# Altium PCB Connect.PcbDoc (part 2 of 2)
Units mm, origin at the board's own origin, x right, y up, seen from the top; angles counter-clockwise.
Board outline 500 x 50 mm, 2 copper layers (Top Layer, Bottom Layer); 349 components, 200 nets, 1152 pads, 307 vias.
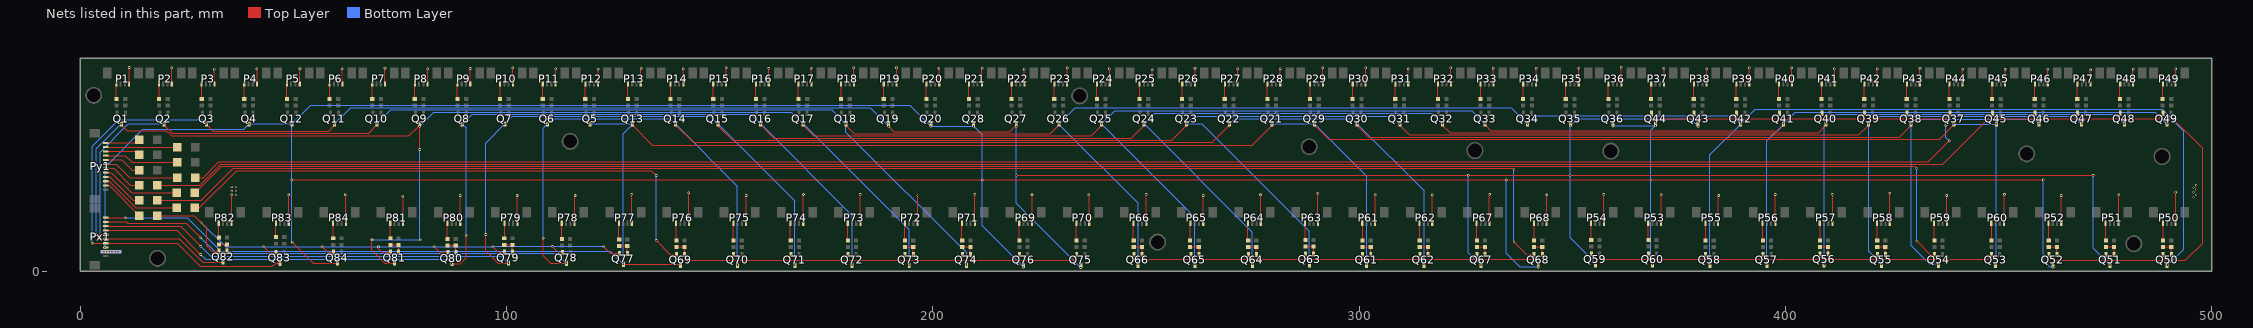
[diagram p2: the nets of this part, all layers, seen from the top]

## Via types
v1: diameter 0.6, hole 0.3, Top Layer to Bottom Layer, 196 vias
v2: diameter 0.5, hole 0.3, Top Layer to Bottom Layer, 111 vias

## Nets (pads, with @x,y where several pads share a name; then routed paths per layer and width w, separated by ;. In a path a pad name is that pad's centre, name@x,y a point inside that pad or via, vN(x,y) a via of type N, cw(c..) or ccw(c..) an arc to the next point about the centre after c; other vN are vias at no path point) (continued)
NetD6_1: D6.1 Q37.2 Q38.2 Q39.2 Q40.2 Q41.2 Q42.2 Q43.2 Q44.2 | length 499.5
  Top Layer w0.254: D6.1@26.992,21.971 28.829,21.971 32.512,25.654 433.451,25.654 v1(438.404,30.607) ; Q44.2@368.556,37.064 368.556,36.828 369.57,35.814 378.587,35.814 ; Q43.2@378.552,37.064 378.552,35.849 378.587,35.814 ; Q42.2@388.548,37.064 388.548,35.886 388.62,35.814 ; Q41.2@398.544,37.064 398.544,35.832 398.526,35.814 ; Q40.2@408.54,37.064 408.54,35.833 408.559,35.814 ; Q39.2@418.536,37.064 418.536,35.885 418.465,35.814 ; Q38.2@428.532,37.064 428.532,35.848 428.498,35.814 ; v1(437.642,34.29) 437.642,35.814 ; Q37.2@438.528,37.064 438.528,36.7 437.642,35.814 ; 378.587,35.814 388.62,35.814 ; 388.62,35.814 398.526,35.814 ; 398.526,35.814 408.559,35.814 ; 408.559,35.814 418.465,35.814 ; 418.465,35.814 428.498,35.814 ; 428.498,35.814 437.642,35.814
  Bottom Layer w0.254: v1(437.642,34.29) 437.642,31.369 v1(438.404,30.607)
NetD7_1: D7.1 Q45.2 Q46.2 Q47.2 Q48.2 Q49.2 Q50.2 Q51.2 Q52.2 | length 558.7
  Top Layer w0.254: D7.1@18.102,20.193 28.067,20.193 33.02,25.146 436.927,25.146 Q45.2@448.524,36.743 ; Q45.2@448.524,37.064 Q45.2@448.524,36.743 ; Q46.2@458.52,37.064 458.52,35.864 458.47,35.814 ; Q52.2@461.759,3.937 461.759,3.569 462.788,2.54 475.107,2.54 ; Q47.2@468.516,37.064 468.516,35.827 468.503,35.814 ; Q51.2@475.171,3.937 475.171,2.604 475.107,2.54 ; Q48.2@478.512,37.064 478.512,35.838 478.536,35.814 ; Q49.2@488.508,37.064 Q49.2@488.508,36.769 ; Q50.2@488.583,3.937 488.583,2.54 ; Q45.2@448.524,36.743 449.453,35.814 458.47,35.814 ; 458.47,35.814 468.503,35.814 ; 468.503,35.814 478.536,35.814 ; 475.107,2.54 488.583,2.54 ; 478.536,35.814 487.553,35.814 Q49.2@488.508,36.769 ; Q49.2@488.508,36.769 488.508,36.764 489.331,35.941 490.728,35.941 497.84,28.829 497.84,6.604 493.776,2.54 488.583,2.54
NetD8_1: D8.1 Q53.2 Q54.2 Q55.2 Q56.2 Q57.2 Q58.2 Q59.2 Q60.2 | length 531.3
  Top Layer w0.254: D8.1@26.865,18.415 27.007,18.415 33.23,24.638 430.276,24.638 v2(430.784,24.13) ; Q59.2@354.464,4.064 354.464,3.803 355.473,2.794 381.254,2.794 ; 367.876,2.921 Q60.2@367.876,4.064 ; Q58.2@381.287,3.937 381.287,2.827 381.254,2.794 ; Q57.2@394.699,3.937 394.699,2.811 394.716,2.794 ; Q56.2@408.111,3.937 408.111,2.854 408.051,2.794 ; Q55.2@421.523,3.937 421.523,2.804 421.513,2.794 ; v2(430.784,7.112) 433.959,3.937 Q54.2@434.935,3.937 434.935,2.794 ; Q53.2@448.347,3.937 448.347,3.593 447.548,2.794 434.935,2.794 ; 381.254,2.794 394.716,2.794 ; 394.716,2.794 408.051,2.794 ; 408.051,2.794 421.513,2.794 ; 421.513,2.794 434.935,2.794
  Bottom Layer w0.254: v2(430.784,7.112) v2(430.784,24.13)
NetD9_1: D9.1 Q61.2 Q62.2 Q63.2 Q64.2 Q65.2 Q66.2 Q67.2 Q68.2 | length 446.6
  Top Layer w0.254: D9.1@18.102,16.637 28.448,16.637 35.941,24.13 336.042,24.13 v2(336.296,23.876) ; Q66.2@247.168,3.937 247.168,3.657 248.031,2.794 260.477,2.794 ; Q65.2@260.499,3.937 260.499,2.816 260.477,2.794 ; Q64.2@273.992,3.937 273.992,2.868 274.066,2.794 ; Q63.2@287.404,4.064 287.404,2.797 287.401,2.794 ; Q61.2@300.816,3.937 300.816,2.874 300.736,2.794 ; Q62.2@314.228,3.937 314.228,2.824 314.198,2.794 ; Q67.2@327.64,3.937 327.64,2.814 327.66,2.794 ; v2(336.296,6.985) 339.344,3.937 Q68.2@341.052,3.937 341.052,3.613 340.233,2.794 327.66,2.794 ; 260.477,2.794 274.066,2.794 ; 274.066,2.794 287.401,2.794 ; 287.401,2.794 300.736,2.794 ; 300.736,2.794 314.198,2.794 ; 314.198,2.794 327.66,2.794
  Bottom Layer w0.254: v2(336.296,6.985) v2(336.296,23.876)
NetD10_1: D10.1 Q69.2 Q70.2 Q71.2 Q72.2 Q73.2 Q74.2 Q75.2 Q76.2 | length 237.7
  Top Layer w0.254: D10.1@26.865,14.859 27.94,14.859 36.703,23.622 133.985,23.622 v1(135.128,22.479) ; v1(135.128,7.239) 138.43,3.937 Q69.2@139.873,3.937 139.873,3.637 140.97,2.54 153.285,2.54 ; Q70.2@153.285,3.937 153.285,2.54 ; Q71.2@166.697,3.937 166.697,2.613 166.624,2.54 ; Q72.2@180.109,3.937 180.109,2.563 180.086,2.54 ; Q73.2@193.521,3.937 193.521,2.567 193.548,2.54 ; Q74.2@206.933,3.937 206.933,2.617 207.01,2.54 ; Q76.2@220.345,3.937 220.345,2.54 ; Q75.2@233.757,3.937 233.757,3.633 232.664,2.54 220.345,2.54 ; 153.285,2.54 166.624,2.54 ; 166.624,2.54 180.086,2.54 ; 180.086,2.54 193.548,2.54 ; 193.548,2.54 207.01,2.54 ; 207.01,2.54 220.345,2.54
  Bottom Layer w0.254: v1(135.128,7.239) 135.001,7.366 135.128,7.493 v1(135.128,22.479)
NetD11_1: D11.1 Q77.2 Q78.2 Q79.2 Q80.2 Q81.2 Q82.2 Q83.2 Q84.2 | length 141.6
  Top Layer w0.254: D11.1@18.102,13.081 26.797,13.081 v2(28.448,11.43) 29.718,10.16 29.718,5.969 31.008,4.679 Q82.2@32.578,4.679 ; v1(43.053,5.715) 44.363,4.405 Q83.2@45.913,4.405 ; v1(56.769,5.715) 58.039,4.445 Q84.2@59.402,4.445 ; v1(69.977,5.715) 69.977,5.334 70.866,4.445 Q81.2@72.814,4.445 ; v1(83.058,5.715) 84.455,4.318 Q80.2@86.226,4.318 ; v1(96.774,5.715) 98.044,4.445 Q79.2@99.51,4.445 ; v1(110.744,5.842) 112.181,4.405 Q78.2@113.096,4.405 ; v1(122.809,5.715) 124.333,4.191 Q77.2@126.461,4.191
  Bottom Layer w0.254: v2(28.448,11.43) 34.163,5.715 v1(43.053,5.715) v1(56.769,5.715) v1(69.977,5.715) v1(83.058,5.715) v1(96.774,5.715) 96.901,5.842 v1(110.744,5.842) 122.682,5.842 v1(122.809,5.715)
NetP1_4: P1.4 R85.2 | length 3.5
  Top Layer w0.254: P1.4@8.5,43.925 8.5,40.403 R85.2@8.509,40.394
NetP2_4: P2.4 R86.2 | length 3.5
  Top Layer w0.254: P2.4@18.5,43.925 18.5,40.402 R86.2@18.508,40.394
NetP3_4: P3.4 R87.2 | length 3.5
  Top Layer w0.254: P3.4@28.5,43.925 28.5,40.4 R87.2@28.506,40.394
NetP4_4: P4.4 R88.2 | length 3.5
  Top Layer w0.254: P4.4@38.5,43.925 38.5,40.399 R88.2@38.505,40.394
NetP5_4: P5.4 R89.2 | length 3.5
  Top Layer w0.254: P5.4@48.5,43.925 48.503,43.922 R89.2@48.503,40.394
NetP6_4: P6.4 R90.2 | length 3.5
  Top Layer w0.254: P6.4@58.5,43.925 58.502,43.923 R90.2@58.502,40.394
NetP7_4: P7.4 R91.2 | length 3.5
  Top Layer w0.254: R91.2@68.501,40.394 P7.4@68.501,43.924
NetP8_4: P8.4 R92.2 | length 3.5
  Top Layer w0.254: R92.2@78.499,40.394 P8.4@78.499,43.924
NetP9_4: P9.4 R93.2 | length 3.5
  Top Layer w0.254: R93.2@88.498,40.394 88.498,43.923 P9.4@88.5,43.925
NetP10_4: P10.4 R94.2 | length 3.5
  Top Layer w0.254: R94.2@98.496,40.394 98.496,43.921 P10.4@98.5,43.925
NetP11_4: P11.4 R95.2 | length 3.5
  Top Layer w0.254: R95.2@108.495,40.394 108.495,43.92 P11.4@108.5,43.925
NetP12_4: P12.4 R96.2 | length 3.5
  Top Layer w0.254: R96.2@118.494,40.394 118.494,43.919 P12.4@118.5,43.925
NetP13_4: P13.4 R97.2 | length 3.5
  Top Layer w0.254: R97.2@128.492,40.394 128.492,43.917 P13.4@128.5,43.925
NetP14_4: P14.4 R98.2 | length 3.5
  Top Layer w0.254: R98.2@138.491,40.394 138.491,43.916 P14.4@138.5,43.925
NetP15_4: P15.4 R99.2 | length 3.5
  Top Layer w0.254: R99.2@148.489,40.394 148.489,43.914 P15.4@148.5,43.925
NetP16_4: P16.4 R100.2 | length 3.5
  Top Layer w0.254: R100.2@158.488,40.394 158.488,43.913 P16.4@158.5,43.925
NetP17_4: P17.4 R101.2 | length 3.5
  Top Layer w0.254: R101.2@168.487,40.394 168.487,43.912 P17.4@168.5,43.925
NetP18_4: P18.4 R102.2 | length 3.5
  Top Layer w0.254: R102.2@178.485,40.394 178.485,43.91 P18.4@178.5,43.925
NetP19_4: P19.4 R103.2 | length 3.5
  Top Layer w0.254: R103.2@188.484,40.394 188.484,43.909 P19.4@188.5,43.925
NetP20_4: P20.4 R104.2 | length 3.5
  Top Layer w0.254: R104.2@198.482,40.394 198.482,43.907 P20.4@198.5,43.925
NetP21_4: P21.4 R105.2 | length 3.5
  Top Layer w0.254: R105.2@208.481,40.394 208.481,43.906 P21.4@208.5,43.925
NetP22_4: P22.4 R106.2 | length 3.5
  Top Layer w0.254: R106.2@218.48,40.394 218.48,43.905 P22.4@218.5,43.925
NetP23_4: P23.4 R107.2 | length 3.5
  Top Layer w0.254: R107.2@228.478,40.394 228.478,43.903 P23.4@228.5,43.925
NetP24_4: P24.4 R108.2 | length 3.5
  Top Layer w0.254: R108.2@238.477,40.394 238.477,43.902 P24.4@238.5,43.925
NetP25_4: P25.4 R109.2 | length 3.5
  Top Layer w0.254: R109.2@248.475,40.394 248.475,43.901 P25.4@248.5,43.925
NetP26_4: P26.4 R110.2 | length 3.5
  Top Layer w0.254: R110.2@258.474,40.394 258.474,43.899 P26.4@258.5,43.925
NetP27_4: P27.4 R111.2 | length 3.5
  Top Layer w0.254: R111.2@268.473,40.394 268.473,43.898 P27.4@268.5,43.925
NetP28_4: P28.4 R112.2 | length 3.5
  Top Layer w0.254: R112.2@278.471,40.394 278.471,43.896 P28.4@278.5,43.925
NetP29_4: P29.4 R113.2 | length 3.5
  Top Layer w0.254: R113.2@288.47,40.394 288.47,43.895 P29.4@288.5,43.925
NetP30_4: P30.4 R114.2 | length 3.5
  Top Layer w0.254: R114.2@298.468,40.394 298.468,43.894 P30.4@298.5,43.925
NetP31_4: P31.4 R115.2 | length 3.5
  Top Layer w0.254: R115.2@308.467,40.394 308.467,43.892 P31.4@308.5,43.925
NetP32_4: P32.4 R116.2 | length 3.5
  Top Layer w0.254: R116.2@318.466,40.394 318.466,43.891 P32.4@318.5,43.925
NetP33_4: P33.4 R117.2 | length 3.5
  Top Layer w0.254: R117.2@328.464,40.394 328.464,43.889 P33.4@328.5,43.925
NetP34_4: P34.4 R118.2 | length 3.5
  Top Layer w0.254: R118.2@338.463,40.394 338.463,43.888 P34.4@338.5,43.925
NetP35_4: P35.4 R119.2 | length 3.5
  Top Layer w0.254: R119.2@348.462,40.394 348.462,43.887 P35.4@348.5,43.925
NetP36_4: P36.4 R120.2 | length 3.5
  Top Layer w0.254: R120.2@358.46,40.394 358.46,43.885 P36.4@358.5,43.925
NetP37_4: P37.4 R121.2 | length 3.5
  Top Layer w0.254: R121.2@368.459,40.394 368.459,43.884 P37.4@368.5,43.925
NetP38_4: P38.4 R122.2 | length 3.5
  Top Layer w0.254: R122.2@378.457,40.394 378.457,43.882 P38.4@378.5,43.925
NetP39_4: P39.4 R123.2 | length 3.5
  Top Layer w0.254: R123.2@388.456,40.394 388.456,43.881 P39.4@388.5,43.925
NetP40_4: P40.4 R124.2 | length 3.5
  Top Layer w0.254: R124.2@398.455,40.394 398.455,43.88 P40.4@398.5,43.925
NetP41_4: P41.4 R125.2 | length 3.6
  Top Layer w0.254: R125.2@408.453,40.394 408.453,43.878 P41.4@408.5,43.925
NetP42_4: P42.4 R126.2 | length 3.6
  Top Layer w0.254: R126.2@418.452,40.394 418.452,43.877 P42.4@418.5,43.925
NetP43_4: P43.4 R127.2 | length 3.6
  Top Layer w0.254: R127.2@428.45,40.394 428.45,43.875 P43.4@428.5,43.925
NetP44_4: P44.4 R128.2 | length 3.6
  Top Layer w0.254: R128.2@438.449,40.394 438.449,43.874 P44.4@438.5,43.925
NetP45_4: P45.4 R129.2 | length 3.6
  Top Layer w0.254: R129.2@448.448,40.394 448.448,43.873 P45.4@448.5,43.925
NetP46_4: P46.4 R130.2 | length 3.6
  Top Layer w0.254: R130.2@458.446,40.394 458.446,43.871 P46.4@458.5,43.925
NetP47_4: P47.4 R131.2 | length 3.6
  Top Layer w0.254: R131.2@468.445,40.394 468.445,43.87 P47.4@468.5,43.925
NetP48_4: P48.4 R132.2 | length 3.6
  Top Layer w0.254: R132.2@478.443,40.394 478.443,43.868 P48.4@478.5,43.925
NetP49_4: P49.4 R133.2 | length 3.6
  Top Layer w0.254: R133.2@488.442,40.394 488.442,43.867 P49.4@488.5,43.925
NetP50_4: P50.4 R134.2 | length 4
  Top Layer w0.254: P50.4@488.5,11.268 488.569,11.199 R134.2@488.569,7.247
NetP51_4: P51.4 R135.2 | length 4
  Top Layer w0.254: P51.4@475.088,11.268 475.156,11.2 R135.2@475.156,7.247
NetP52_4: P52.4 R136.2 | length 4
  Top Layer w0.254: P52.4@461.677,11.268 461.744,11.2 R136.2@461.744,7.247
NetP53_4: P53.4 R137.2 | length 3.9
  Top Layer w0.254: P53.4@367.795,11.268 367.858,11.205 R137.2@367.858,7.374
NetP54_4: P54.4 R138.2 | length 3.9
  Top Layer w0.254: P54.4@354.383,11.268 354.445,11.206 R138.2@354.445,7.374
NetP55_4: P55.4 R139.2 | length 4
  Top Layer w0.254: P55.4@381.207,11.268 381.27,11.205 R139.2@381.27,7.247
NetP56_4: P56.4 R140.2 | length 4
  Top Layer w0.254: P56.4@394.618,11.268 394.682,11.204 R140.2@394.682,7.247
NetP57_4: P57.4 R141.2 | length 4
  Top Layer w0.254: P57.4@408.03,11.268 408.095,11.203 R141.2@408.095,7.247
NetP58_4: P58.4 R142.2 | length 4
  Top Layer w0.254: P58.4@421.442,11.268 421.507,11.203 R142.2@421.507,7.247
NetP59_4: P59.4 R143.2 | length 4
  Top Layer w0.254: P59.4@434.853,11.268 434.919,11.202 R143.2@434.919,7.247
NetP60_4: P60.4 R144.2 | length 4
  Top Layer w0.254: P60.4@448.265,11.268 448.332,11.201 R144.2@448.332,7.247
NetP61_4: P61.4 R145.2 | length 4
  Top Layer w0.254: P61.4@300.736,11.268 300.796,11.209 R145.2@300.796,7.247
NetP62_4: P62.4 R146.2 | length 4
  Top Layer w0.254: P62.4@314.148,11.268 314.208,11.208 R146.2@314.208,7.247
NetP63_4: P63.4 R147.2 | length 4
  Top Layer w0.254: P63.4@287.325,11.268 287.325,7.374 R147.2@287.383,7.374
NetP64_4: P64.4 R148.2 | length 4.1
  Top Layer w0.254: P64.4@273.913,11.268 273.913,7.247 R148.2@273.971,7.247
NetP65_4: P65.4 R149.2 | length 4.3
  Top Layer w0.254: R149.2@260.42,6.985 P65.4@260.42,11.268
NetP66_4: P66.4 R150.2 | length 4.1
  Top Layer w0.254: P66.4@247.066,11.268 247.066,7.247 R150.2@247.146,7.247
NetP67_4: P67.4 R151.2 | length 4
  Top Layer w0.254: P67.4@327.56,11.268 327.62,11.207 R151.2@327.62,7.247
NetP68_4: P68.4 R152.2 | length 4
  Top Layer w0.254: P68.4@340.971,11.268 341.033,11.207 R152.2@341.033,7.247
NetP69_4: P69.4 R153.2 | length 4.1
  Top Layer w0.254: P69.4@220.243,11.268 220.243,7.247 R153.2@220.322,7.247
NetP70_4: P70.4 R154.2 | length 4.1
  Top Layer w0.254: P70.4@233.655,11.268 233.655,7.247 R154.2@233.734,7.247
NetP71_4: P71.4 R155.2 | length 4.1
  Top Layer w0.254: P71.4@206.832,11.268 206.832,7.247 R155.2@206.909,7.247
NetP72_4: P72.4 R156.2 | length 4.3
  Top Layer w0.254: P72.4@193.421,11.43 193.421,7.247 R156.2@193.497,7.247
NetP73_4: P73.4 R157.2 | length 4.1
  Top Layer w0.254: P73.4@180.01,11.268 180.01,7.247 R157.2@180.084,7.247
NetP74_4: P74.4 R158.2 | length 4.1
  Top Layer w0.254: P74.4@166.599,11.268 166.599,7.247 R158.2@166.672,7.247
NetP75_4: P75.4 R159.2 | length 4.1
  Top Layer w0.254: P75.4@153.187,11.268 153.187,7.247 R159.2@153.26,7.247
NetP76_4: P76.4 R160.2 | length 4.1
  Top Layer w0.254: P76.4@139.776,11.268 139.776,7.247 R160.2@139.847,7.247
NetP77_4: P77.4 R161.2 | length 4.1
  Top Layer w0.254: R161.2@126.365,7.247 R161.2@126.365,7.501 ; P77.4@126.365,11.303 R161.2@126.365,7.501 ; R161.2@126.435,7.501 R161.2@126.365,7.501
NetP78_4: P78.4 R162.2 | length 4.1
  Top Layer w0.254: R162.2@112.954,7.247 R162.2@112.954,7.628 ; P78.4@112.954,11.268 R162.2@112.954,7.628 ; R162.2@113.023,7.628 R162.2@112.954,7.628
NetP79_4: P79.4 R163.2 | length 3.9
  Top Layer w0.254: R163.2@99.434,7.755 R163.2@99.483,7.755 ; R163.2@99.561,7.374 P79.4@99.561,11.268
NetP80_4: P80.4 R164.2 | length 3.7
  Top Layer w0.254: P80.4@86.15,11.268 86.15,7.628 R164.2@86.198,7.628
NetP81_4: P81.4 R165.2 | length 3.4
  Top Layer w0.254: P81.4@72.72,11.049 72.72,7.755 R165.2@72.786,7.755
NetP82_4: P82.4 R166.2 | length 3.5
  Top Layer w0.254: P82.4@32.503,11.268 32.503,9.957 32.487,9.94 32.487,7.882 R166.2@32.549,7.882
NetP83_4: P83.4 R167.2 | length 3.1
  Top Layer w0.254: P83.4@45.898,11.049 45.898,8.009 R167.2@45.961,8.009
NetP84_4: P84.4 R168.2 | length 3.5
  Top Layer w0.254: R168.2@59.326,7.755 P84.4@59.326,11.268
P00: Px1.1 Q5.3 Q13.3 Q21.3 Q29.3 Q37.3 Q45.3 Q53.3 Q61.3 Q69.3 Q77.3 | length 581.6
  Top Layer w0.254: Px1.1@6.004,12.587 10.527,12.587 v1(10.541,12.573) ; Q77.3@127.411,1.691 140.569,1.691 Q69.3@140.823,1.437 ; Q13.3@129.603,34.564 129.603,34.227 134.239,29.591 274.955,29.591 279.543,34.179 v1(279.543,34.564) ; v1(289.56,34.544) 289.56,34.29 292.862,30.988 436.118,30.988 439.478,34.348 v1(439.478,34.564)
  Bottom Layer w0.254: v1(10.541,12.573) 25.146,12.573 33.02,4.699 124.333,4.699 v1(127.381,1.651) 127.381,32.258 v1(129.667,34.544) 129.647,34.564 v1(119.608,34.564) ; v1(279.543,34.564) 289.54,34.564 v1(289.56,34.544) 301.752,22.352 v1(301.752,1.778) ; v1(439.478,34.564) 439.498,34.544 v1(449.453,34.544) 449.453,1.905 v1(449.326,1.778)
P01: Px1.2 Q6.3 Q14.3 Q22.3 Q30.3 Q38.3 Q46.3 Q54.3 Q62.3 Q70.3 Q78.3 | length 624.4
  Top Layer w0.254: Px1.2@6.004,11.587 10.765,11.587 11.049,11.303 24.892,11.303 v1(28.321,7.874) ; v1(108.585,7.747) 108.585,3.683 110.363,1.905 v1(114.046,1.905) ; v1(139.599,34.564) 139.599,34.391 143.764,30.226 265.557,30.226 269.547,34.216 v1(269.547,34.564) ; v1(299.593,34.544) 299.593,34.163 302.26,31.496 426.72,31.496 429.482,34.258 v1(429.482,34.564)
  Bottom Layer w0.254: v1(28.321,7.874) 32.004,4.191 111.76,4.191 v1(114.046,1.905) ; v1(108.585,7.747) 108.585,33.537 v1(109.612,34.564) 110.862,35.814 138.349,35.814 v1(139.599,34.564) 154.178,19.985 v1(154.178,1.397) ; v1(269.547,34.564) 270.797,35.814 298.323,35.814 v1(299.593,34.544) 315.214,18.923 v1(315.214,1.778) ; v1(435.864,1.778) 433.705,1.778 429.482,6.001 v1(429.482,34.564) 430.605,35.687 458.347,35.687 v1(459.47,34.564)
P02: Px1.3 Q7.3 Q15.3 Q23.3 Q31.3 Q39.3 Q47.3 Q55.3 Q63.3 Q71.3 Q79.3 | length 638.3
  Top Layer w0.254: Px1.3@6.004,10.587 23.576,10.587 v1(28.321,5.842) ; v1(95.123,8.636) 95.123,4.826 98.044,1.905 v1(100.457,1.905) ; Q79.3@100.461,1.655 Q79.3@100.461,1.945 ; v1(149.595,34.564) 149.595,34.174 153.035,30.734 256.032,30.734 259.551,34.253 v1(259.551,34.564) ; v1(309.531,34.564) 309.531,34.258 311.785,32.004 417.195,32.004 419.486,34.295 v1(419.486,34.564)
  Bottom Layer w0.254: v1(28.321,5.842) 30.607,3.556 98.806,3.556 v1(100.457,1.905) ; v1(95.123,8.636) 95.123,30.071 v1(99.616,34.564) 101.374,36.322 147.837,36.322 v1(149.595,34.564) 167.64,16.519 v1(167.64,1.397) ; v1(288.29,1.905) 288.29,9.398 263.124,34.564 v1(259.551,34.564) 261.309,36.322 307.773,36.322 v1(309.531,34.564) ; v1(422.529,1.651) 419.486,4.694 v1(419.486,34.564) 421.244,36.322 467.741,36.322 v1(469.519,34.544)
P03: Px1.4 Q8.3 Q16.3 Q24.3 Q32.3 Q40.3 Q48.3 Q56.3 Q64.3 Q72.3 Q80.3 | length 639.5
  Top Layer w0.254: Px1.4@6.004,9.587 22.671,9.587 v1(28.321,3.937) ; v1(87.122,1.778) 89.154,1.778 90.551,3.175 v1(90.551,8.509) ; Q8.3@89.62,34.564 89.642,34.564 v1(89.662,34.544) ; v1(159.591,34.564) 159.591,34.338 162.687,31.242 246.507,31.242 249.555,34.29 v1(249.555,34.564) ; v1(319.532,34.559) 319.532,34.29 321.31,32.512 407.797,32.512 409.49,34.205 v1(409.49,34.564)
  Bottom Layer w0.254: v1(28.321,3.937) 29.464,2.794 86.106,2.794 v1(87.122,1.778) ; v1(90.551,8.509) 90.551,33.655 v1(89.662,34.544) 91.948,36.83 157.325,36.83 v1(159.591,34.564) 181.102,13.053 v1(181.102,1.397) ; v1(274.955,1.778) 274.955,9.164 v1(249.555,34.564) 252.075,37.084 317.007,37.084 v1(319.532,34.559) ; v1(409.067,1.524) 409.067,34.141 v1(409.49,34.564) 411.756,36.83 477.196,36.83 v1(479.462,34.564)
P04: Px1.5 Q1.3 Q9.3 Q17.3 Q25.3 Q33.3 Q41.3 Q49.3 Q57.3 Q65.3 Q73.3 Q81.3 | length 691.3
  Top Layer w0.254: v1(3.81,8.636) 5.955,8.636 Px1.5@6.004,8.587 ; v1(9.652,34.564) 9.652,34.417 11.049,33.02 20.193,33.02 21.463,31.75 77.089,31.75 79.375,34.036 v1(79.629,34.036) v1(79.629,28.575) ; v1(68.453,7.366) 68.453,4.953 71.461,1.945 Q81.3@73.764,1.945 ; v1(169.587,34.564) 169.587,34.248 172.085,31.75 237.109,31.75 239.559,34.2 v1(239.559,34.564) ; Q33.3@329.523,34.564 329.523,34.332 330.835,33.02 398.272,33.02 399.494,34.242 Q41.3@399.494,34.564
  Bottom Layer w0.254: v1(3.81,8.636) 3.81,28.722 v1(9.652,34.564) ; v1(68.453,7.366) v1(79.756,7.366) 79.629,7.493 v1(79.629,28.575) ; v1(79.629,34.036) 82.931,37.338 166.813,37.338 v1(169.587,34.564) 194.437,9.714 v1(194.437,1.397) ; v1(261.493,1.651) 261.493,12.63 v1(239.559,34.564) 242.714,37.719 326.39,37.719 v1(329.565,34.544) ; v1(395.605,1.651) 395.605,30.607 v1(399.542,34.544) 402.336,37.338 486.664,37.338 v1(489.458,34.544)
P05: Px1.6 Q2.3 Q10.3 Q18.3 Q26.3 Q34.3 Q42.3 Q50.3 Q58.3 Q66.3 Q74.3 Q82.3 | length 712.4
  Top Layer w0.254: v1(4.699,7.62) 5.971,7.62 Px1.6@6.004,7.587 23.274,7.587 28.702,2.159 33.508,2.159 Q82.3@33.528,2.179 ; v1(19.648,34.564) 19.648,34.327 21.59,32.385 67.691,32.385 69.628,34.322 v1(69.628,34.564) ; v1(179.583,34.564) 179.583,34.285 181.61,32.258 227.584,32.258 229.563,34.237 Q26.3@229.563,34.564
  Bottom Layer w0.254: v1(4.699,7.62) 4.699,27.94 11.323,34.564 v1(19.648,34.564) ; v1(69.628,34.564) 72.91,37.846 176.301,37.846 v1(179.583,34.564) 179.583,32.634 207.899,4.318 v1(207.899,1.397) ; v1(248.158,1.778) 248.158,15.969 v1(229.583,34.544) 233.393,38.354 335.661,38.354 v1(339.471,34.544) 341.376,36.449 387.604,36.449 v1(389.509,34.544) ; v1(382.27,1.778) 382.27,27.305 v1(389.509,34.544) ; v1(489.585,1.397) 493.395,5.207 493.395,32.893 488.315,37.973 392.938,37.973 v1(389.509,34.544)
P06: Px1.7 Q3.3 Q11.3 Q19.3 Q27.3 Q35.3 Q43.3 Q51.3 Q59.3 Q67.3 Q75.3 Q83.3 | length 699.8
  Top Layer w0.254: v1(2.794,6.604) 5.987,6.604 Px1.7@6.004,6.587 22.75,6.587 28.194,1.143 45.085,1.143 45.847,1.905 Q83.3@46.863,1.905 ; v1(29.644,34.564) 29.644,34.364 31.115,32.893 58.293,32.893 59.632,34.232 v1(59.632,34.564) ; Q19.3@189.579,34.564 189.579,34.068 v1(189.611,34.036) 190.881,32.766 218.059,32.766 219.329,34.036 v1(219.583,34.036) ; v2(219.587,22.483) v1(325.628,22.483) v2(349.504,22.483) v1(472.19,22.483) ; v1(234.696,0.889) Q75.3@234.823,0.889 ; v1(349.515,34.152) Q35.3@349.515,34.564 ; Q59.3@355.414,1.329 Q59.3@355.414,1.564 ; v1(379.476,34.036) Q43.3@379.603,34.036
  Bottom Layer w0.254: v1(2.794,6.604) 2.794,29.337 9.017,35.56 28.648,35.56 v1(29.644,34.564) ; v1(59.632,34.564) 63.422,38.354 185.293,38.354 v1(189.611,34.036) ; v1(219.583,34.036) 219.587,34.032 v2(219.587,22.483) 219.587,16.006 219.583,16.002 v1(234.696,0.889) ; v1(325.628,22.483) 325.628,4.399 v1(328.59,1.437) ; v1(355.473,1.905) 349.515,7.863 v1(349.515,34.152) 351.176,35.814 377.698,35.814 v1(379.476,34.036) ; v1(472.19,22.483) 472.19,5.376 472.186,5.372 v2(476.121,1.437)
P07: Px1.8 Q4.3 Q12.3 Q20.3 Q28.3 Q36.3 Q44.3 Q52.3 Q60.3 Q68.3 Q76.3 Q84.3 | length 812.6
  Top Layer w0.254: v1(49.636,21.463) v2(211.582,21.463) v1(334.518,21.463) v2(368.427,21.463) v1(460.502,21.463) ; v1(49.784,6.858) 54.697,1.945 Q84.3@60.352,1.945 Q84.3@60.352,1.651 ; v1(199.517,34.036) 199.575,34.094 Q20.3@199.575,34.564 ; v1(221.234,1.016) Q76.3@221.361,1.016 ; Q68.3@342.002,1.437 342.002,1.025 v1(342.011,1.016) ; Q36.3@359.51,34.564 359.51,34.063 v1(359.537,34.089) ; Q44.3@369.443,34.163 v1(369.496,34.11)
  Bottom Layer w0.254: v1(5.842,5.588) 5.842,24.384 14.732,33.274 38.35,33.274 v1(39.64,34.564) v1(49.636,34.564) ; v1(49.784,6.858) 49.636,7.006 v1(49.636,21.463) v1(49.636,34.564) ; v1(221.234,1.016) 211.582,10.668 v2(211.582,21.463) 211.582,32.004 v1(209.55,34.036) v1(199.517,34.036) 194.564,38.989 54.061,38.989 v1(49.636,34.564) ; v1(334.518,21.463) 334.518,4.191 337.693,1.016 v1(342.011,1.016) ; v1(359.537,34.089) v1@369.475,34.089 ; v1(368.808,1.651) 368.427,2.032 v2(368.427,21.463) 368.427,33.041 v1@369.475,34.089 ; v1(369.496,34.11) v1@369.475,34.089 ; v1(460.502,21.463) 460.502,2.413 461.899,1.016 v1(462.661,1.016)
P11: D1.2 Py1.1 | length 8.2
  Top Layer w0.254: Py1.1@6.004,30.138 13.179,30.138 D1.2@13.902,30.861
P12: D2.2 Py1.2 | length 16.8
  Top Layer w0.254: Py1.2@6.004,29.138 22.737,29.138 D2.2@22.792,29.083
P13: D3.2 Py1.3 | length 8.2
  Top Layer w0.254: Py1.3@6.004,28.138 13.069,28.138 D3.2@13.902,27.305
P14: D4.2 Py1.4 | length 17.5
  Top Layer w0.254: Py1.4@6.004,27.138 10.581,27.138 12.192,25.527 D4.2@22.792,25.527
P15: D5.2 Py1.5 | length 8.9
  Top Layer w0.254: Py1.5@6.004,26.138 9.803,26.138 12.192,23.749 D5.2@13.902,23.749
P16: D6.2 Py1.6 | length 18.1
  Top Layer w0.254: Py1.6@6.004,25.138 8.517,25.138 11.684,21.971 D6.2@22.792,21.971
P17: D7.2 Py1.7 | length 9.5
  Top Layer w0.254: Py1.7@6.004,24.138 7.866,24.138 11.811,20.193 D7.2@13.902,20.193
P24: D11.2 Py1.11 | length 10.8
  Top Layer w0.254: Py1.11@6.004,20.138 6.845,20.138 D11.2@13.902,13.081
P25: D10.2 Py1.10 | length 19.3
  Top Layer w0.254: Py1.10@6.004,21.138 6.802,21.138 13.081,14.859 D10.2@22.665,14.859
P26: D9.2 Py1.9 | length 10.2
  Top Layer w0.254: Py1.9@6.004,22.138 6.945,22.138 12.446,16.637 D9.2@13.902,16.637
P27: D8.2 Py1.8 | length 18.6
  Top Layer w0.254: Py1.8@6.004,23.138 7.342,23.138 12.065,18.415 D8.2@22.665,18.415
RECORD: Q50.1 R50.2 R134.1 | length 3.7
  Top Layer w0.254: R134.1@488.569,5.707 R50.2@490.474,5.707 490.474,3.946 Q50.1@490.483,3.937
REPLAY: Q74.1 R74.2 R155.1 | length 3.7
  Top Layer w0.254: R155.1@206.909,5.707 R74.2@208.814,5.707 208.833,5.707 Q74.1@208.833,3.937
RHY1: Q61.1 R61.2 R145.1 | length 3.7
  Top Layer w0.254: R145.1@300.796,5.707 R61.2@302.701,5.707 302.701,3.952 Q61.1@302.716,3.937
RHY2: Q62.1 R62.2 R146.1 | length 3.7
  Top Layer w0.254: R146.1@314.208,5.707 R62.2@316.113,5.707 316.113,3.952 Q62.1@316.128,3.937
RHY3: Q55.1 R55.2 R142.1 | length 3.7
  Top Layer w0.254: R142.1@421.507,5.707 R55.2@423.412,5.707 423.412,3.948 Q55.1@423.423,3.937
RHY4: Q56.1 R56.2 R141.1 | length 3.7
  Top Layer w0.254: R141.1@408.095,5.707 R56.2@410,5.707 410,3.948 Q56.1@410.011,3.937
RHY5: Q65.1 R65.2 R149.1 | length 3.8
  Top Layer w0.254: R149.1@260.559,5.707 R65.2@262.382,5.707 262.48,5.707 262.48,3.937 Q65.1@262.399,3.937
RHY6: Q66.1 R66.2 R150.1 | length 3.7
  Top Layer w0.254: R150.1@247.146,5.707 R66.2@249.051,5.707 249.068,5.707 Q66.1@249.068,3.937
RHY7: Q67.1 R67.2 R151.1 | length 3.7
  Top Layer w0.254: R151.1@327.62,5.707 R67.2@329.526,5.707 329.526,3.951 Q67.1@329.54,3.937
RHY8: Q68.1 R68.2 R152.1 | length 3.7
  Top Layer w0.254: R152.1@341.033,5.707 R68.2@342.938,5.707 342.938,3.951 Q68.1@342.952,3.937
RHY9: Q63.1 R63.2 R147.1 | length 3.7
  Top Layer w0.254: R147.1@287.383,5.834 R63.2@289.288,5.834 289.304,5.834 Q63.1@289.304,4.064
RHY10: Q64.1 R64.2 R148.1 | length 3.7
  Top Layer w0.254: R148.1@273.971,5.707 R64.2@275.876,5.707 275.892,5.707 Q64.1@275.892,3.937
RHY_EDIT: Q69.1 R69.2 R160.1 | length 3.7
  Top Layer w0.254: R160.1@139.847,5.707 R69.2@141.752,5.707 141.773,5.707 Q69.1@141.773,3.937
SINGLE: Q77.1 R77.2 R161.1 | length 3.7
  Top Layer w0.254: R161.1@126.435,5.961 R77.2@128.34,5.961 128.361,5.961 Q77.1@128.361,4.191
STOP: Q73.1 R73.2 R156.1 | length 3.7
  Top Layer w0.254: R156.1@193.497,5.707 R73.2@195.402,5.707 195.421,5.707 Q73.1@195.421,3.937
TEMPO+: Q79.1 R79.2 R163.1 | length 3.7
  Top Layer w0.254: R163.1@99.483,6.215 R79.2@101.388,6.215 101.411,6.215 Q79.1@101.411,4.445
TEMPO-: Q80.1 R80.2 R164.1 | length 3.7
  Top Layer w0.254: R164.1@86.198,6.088 R80.2@88.103,6.088 88.126,6.088 Q80.1@88.126,4.318
TONE1: Q52.1 R52.2 R136.1 | length 3.7
  Top Layer w0.254: R136.1@461.744,5.707 R52.2@463.649,5.707 463.649,3.947 Q52.1@463.659,3.937
TONE2: Q51.1 R51.2 R135.1 | length 3.7
  Top Layer w0.254: R135.1@475.156,5.707 R51.2@477.062,5.707 477.062,3.946 Q51.1@477.071,3.937
VCC: P1.1 P2.1 P3.1 P4.1 P5.1 P6.1 P7.1 P8.1 P9.1 P10.1 P11.1 P12.1 P13.1 P14.1 P15.1 P16.1 P17.1 P18.1 P19.1 P20.1 P21.1 P22.1 P23.1 P24.1 P25.1 P26.1 P27.1 P28.1 P29.1 P30.1 P31.1 P32.1 P33.1 P34.1 P35.1 P36.1 P37.1 P38.1 P39.1 P40.1 P41.1 P42.1 P43.1 P44.1 P45.1 P46.1 P47.1 P48.1 P49.1 P50.1 P51.1 P52.1 P53.1 P54.1 P55.1 P56.1 P57.1 P58.1 P59.1 P60.1 P61.1 P62.1 P63.1 P64.1 P65.1 P66.1 P67.1 P68.1 P69.1 P70.1 P71.1 P72.1 P73.1 P74.1 P75.1 P76.1 P77.1 P78.1 P79.1 P80.1 P81.1 P82.1 P83.1 P84.1 pad.2 Px1.9 | length 414.3
  Top Layer w0.254: v1(11.487,47.809) 11.5,47.809 P1.1@11.5,43.925 ; v1(21.463,47.752) 21.5,47.715 P2.1@21.5,43.925 ; v1(31.496,47.371) 31.5,47.367 P3.1@31.5,43.925 ; P82.1@35.503,11.268 35.503,17.85 v1(35.56,17.907) ; v1(41.471,47.498) 41.5,47.469 P4.1@41.5,43.925 ; v1(48.895,17.907) 48.915,17.887 P83.1@48.915,11.268 ; P5.1@51.5,43.925 51.5,47.436 v1(51.562,47.498) ; v1(61.468,47.498) 61.5,47.466 P6.1@61.5,43.925 ; v1(62.23,17.907) 62.326,17.811 P84.1@62.326,11.268 ; P7.1@71.5,43.925 v1(71.501,47.625) v1(71.501,47.625) ; v1(75.692,17.653) 75.738,17.607 P81.1@75.738,11.268 ; P8.1@81.5,43.925 81.5,47.464 v1(81.534,47.498) ; P80.1@89.15,11.268 89.15,17.776 v1(89.154,17.78) ; P9.1@91.5,43.925 91.5,47.565 v1(91.507,47.565) ; v1(101.473,47.752) 101.5,47.725 P10.1@101.5,43.925 ; v1(102.489,17.78) 102.561,17.708 P79.1@102.561,11.268 ; P11.1@111.5,43.925 111.5,47.492 v1(111.506,47.498) ; P78.1@115.973,11.268 115.973,17.675 v1(116.078,17.78) ; P12.1@121.5,43.925 121.5,47.332 v1(121.539,47.371) ; P77.1@129.385,11.268 129.385,18.006 v1(129.413,18.034) ; P13.1@131.5,43.925 131.5,47.553 v1(131.572,47.625) ; v1(141.478,47.498) 141.5,47.476 P14.1@141.5,43.925 ; v1(142.748,18.415) 142.796,18.367 P76.1@142.796,11.268 ; P15.1@151.5,43.925 151.5,47.741 v1(151.511,47.752) ; P75.1@156.208,11.268 156.208,17.778 v1(156.21,17.78) ; P16.1@161.5,43.925 v1(161.5,47.581) ; P74.1@169.62,11.268 169.62,17.959 v1(169.672,18.012) ; v1(171.45,47.625) 171.5,47.575 P17.1@171.5,43.925 ; v1(181.483,47.752) 181.5,47.735 P18.1@181.5,43.925 ; v1(183.007,18.034) 183.007,11.292 P73.1@183.031,11.268 ; v1(191.484,47.752) 191.5,47.736 P19.1@191.5,43.925 ; P72.1@196.443,11.268 v2(196.443,17.806) ; v1(201.422,47.625) 201.5,47.547 P20.1@201.5,43.925 ; v1(209.804,18.034) 209.855,17.983 P71.1@209.855,11.268 ; P21.1@211.5,43.925 211.5,47.543 v1(211.582,47.625) ; v1(221.488,47.371) 221.5,47.359 P22.1@221.5,43.925 ; P69.1@223.266,11.268 v1(223.266,17.907) ; P23.1@231.5,43.925 231.5,47.731 v1(231.521,47.752) ; v1(236.601,17.907) 236.678,17.83 P70.1@236.678,11.268 ; v1(241.427,47.498) 241.5,47.425 P24.1@241.5,43.925 ; v1(250.063,18.034) 250.09,18.007 P66.1@250.09,11.268 ; v1(251.46,47.244) 251.5,47.204 P25.1@251.5,43.925 ; v1(261.493,47.625) 261.5,47.618 P26.1@261.5,43.925 ; v1(263.398,17.78) 263.398,17.653 263.42,17.631 P65.1@263.42,11.268 ; P27.1@271.5,43.925 271.5,47.472 v1(271.526,47.498) ; v1(276.86,17.907) 276.913,17.854 P64.1@276.913,11.268 ; P28.1@281.5,43.925 v1(281.5,47.557) ; v1(290.322,18.288) 290.325,18.285 P63.1@290.325,11.268 ; v1(291.465,47.752) 291.5,47.717 P29.1@291.5,43.925 ; v1(301.498,47.752) 301.5,47.75 P30.1@301.5,43.925 ; P61.1@303.736,11.268 303.736,17.859 v1(303.784,17.907) ; P31.1@311.5,43.925 311.5,47.467 v1(311.531,47.498) ; P62.1@317.148,11.268 v1(317.148,17.936) ; v1(321.437,47.752) 321.5,47.689 P32.1@321.5,43.925 ; P67.1@330.56,11.268 330.56,18.013 v1(330.581,18.034) ; v1(331.47,47.625) 331.5,47.595 P33.1@331.5,43.925 ; P34.1@341.5,43.925 341.5,47.622 v1(341.503,47.625) ; P68.1@343.971,11.268 343.971,17.835 v1(344.043,17.907) ; P35.1@351.5,43.925 351.5,47.589 v1(351.536,47.625) ; v1(357.378,18.034) 357.383,18.029 P54.1@357.383,11.268 ; v1(361.442,47.879) 361.5,47.821 P36.1@361.5,43.925 ; P53.1@370.795,11.268 370.795,17.862 v1(370.84,17.907) ; v1(371.475,47.625) 371.5,47.6 P37.1@371.5,43.925 ; P38.1@381.5,43.925 381.5,47.49 v1(381.508,47.498) ; P55.1@384.206,11.268 384.206,17.684 v1(384.302,17.78) ; P39.1@391.5,43.925 391.5,47.711 v1(391.541,47.752) ; P56.1@397.618,11.268 v1(397.618,18.015) ; v1(401.447,47.752) 401.5,47.699 P40.1@401.5,43.925 ; v1(410.972,18.034) 411.03,17.976 P57.1@411.03,11.268 ; v1(411.48,47.498) 411.5,47.478 P41.1@411.5,43.925 ; P42.1@421.5,43.925 421.5,47.485 v1(421.513,47.498) ; v1(424.426,18.28) 424.442,18.28 P58.1@424.442,11.268 ; P43.1@431.5,43.925 431.5,47.579 v1(431.546,47.625) ; v1(437.769,17.78) 437.853,17.696 P59.1@437.853,11.268 ; P44.1@441.5,43.925 441.5,47.292 v1(441.579,47.371) ; P60.1@451.265,11.268 451.265,17.941 v1(451.358,18.034) ; P45.1@451.5,43.925 v1(451.5,47.356) ; P46.1@461.5,43.925 461.5,47.353 v1(461.518,47.371) ; P52.1@464.677,11.268 464.677,17.764 v1(464.693,17.78) ; P47.1@471.5,43.925 471.5,47.193 v1(471.551,47.244) ; P51.1@478.088,11.268 478.155,11.335 v1(478.155,17.907) ; P48.1@481.5,43.925 481.5,47.455 v1(481.584,47.371) ; v1(491.49,18.542) 491.5,18.532 P50.1@491.5,11.268 ; v1(491.49,47.498) 491.5,47.488 P49.1@491.5,43.925
  other v2: 5.588,4.572 6.223,4.572 6.858,4.572 7.493,4.572 8.255,4.572 8.89,4.572 495.681,17.272 36.576,17.907 496.316,17.907 495.681,18.542 35.56,18.796 36.576,18.796 496.316,19.177 495.681,19.685 35.56,19.812 36.576,19.812 496.316,20.193
VOL+: Q81.1 R81.2 R165.1 | length 3.7
  Top Layer w0.254: R165.1@72.786,6.215 R81.2@74.691,6.215 74.714,6.215 Q81.1@74.714,4.445
VOL-: Q82.1 R82.2 R166.1 | length 3.6
  Top Layer w0.254: R166.1@32.549,6.342 R82.2@34.454,6.342 34.478,6.342 Q82.1@34.478,4.679
pads on no net: P1.0 P1.3 P2.0 P2.3 P3.0 P3.3 P4.0 P4.3 P5.0 P5.3 P6.0 P6.3 P7.0 P7.3 P8.0 P8.3 P9.0 P9.3 P10.0 P10.3 P11.0 P11.3 P12.0 P12.3 P13.0 P13.3 P14.0 P14.3 P15.0 P15.3 P16.0 P16.3 P17.0 P17.3 P18.0 P18.3 P19.0 P19.3 P20.0 P20.3 P21.0 P21.3 P22.0 P22.3 P23.0 P23.3 P24.0 P24.3 P25.0 P25.3 P26.0 P26.3 P27.0 P27.3 P28.0 P28.3 P29.0 P29.3 P30.0 P30.3 P31.0 P31.3 P32.0 P32.3 P33.0 P33.3 P34.0 P34.3 P35.0 P35.3 P36.0 P36.3 P37.0 P37.3 P38.0 P38.3 P39.0 P39.3 P40.0 P40.3 P41.0 P41.3 P42.0 P42.3 P43.0 P43.3 P44.0 P44.3 P45.0 P45.3 P46.0 P46.3 P47.0 P47.3 P48.0 P48.3 P49.0 P49.3 P50.0 P50.3 P51.0 P51.3 P52.0 P52.3 P53.0 P53.3 P54.0 P54.3 P55.0 P55.3 P56.0 P56.3 P57.0 P57.3 P58.0 P58.3 P59.0 P59.3 P60.0 P60.3 P61.0 P61.3 P62.0 P62.3 P63.0 P63.3 P64.0 P64.3 P65.0 P65.3 P66.0 P66.3 P67.0 P67.3 P68.0 P68.3 P69.0 P69.3 P70.0 P70.3 P71.0 P71.3 P72.0 P72.3 P73.0 P73.3 P74.0 P74.3 P75.0 P75.3 P76.0 P76.3 P77.0 P77.3 P78.0 P78.3 P79.0 P79.3 P80.0 P80.3 P81.0 P81.3 P82.0 P82.3 P83.0 P83.3 P84.0 P84.3 Px1.0 Py1.0 Py1.12

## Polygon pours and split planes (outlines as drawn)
GND on Top Layer "GND_L01_P000" (hatched 90Degree grid 0 track 0.254, remove dead copper, pour order 0): 0,0 0,50 500,50 500,0
GND on Bottom Layer "GND_L02_P002" (hatched 90Degree grid 0 track 0.254, remove dead copper, pour order 2): 0,0 0,50 500,50 500,0

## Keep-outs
Keep-Out Layer:
  the board outline again, w0.127

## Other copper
Top Layer:
  rectangle net VCC: 5.207,4.191 9.271,4.953
  rectangle net VCC: 34.925,16.891 496.57,20.574
Bottom Layer:
  rectangle net VCC: 6.985,4.191 9.906,20.32
  rectangle net VCC: 6.985,17.145 37.592,20.447
  rectangle net VCC: 495.046,17.018 496.951,48.895
  rectangle net VCC: 7.747,45.339 496.824,48.895

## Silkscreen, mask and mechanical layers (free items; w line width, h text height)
Top Overlay:
  text "C4" at 7.112,34.036 h3 r90
  text "C4#" at 17.108,34.036 h3 r90
  text "D4" at 27.104,34.036 h3 r90
  text "D4#" at 37.1,34.036 h3 r90
  text "E4" at 47.096,34.036 h3 r90
  text "F4" at 57.092,34.036 h3 r90
  text "F4#" at 67.088,34.036 h3 r90
  text "G4" at 77.084,34.036 h3 r90
  text "G4#" at 87.08,34.036 h3 r90
  text "A4" at 97.076,34.036 h3 r90
  text "A4#" at 107.072,34.036 h3 r90
  text "B4" at 117.068,34.036 h3 r90
  text "C5" at 127.063,34.036 h3 r90
  text "C5#" at 137.059,34.036 h3 r90
  text "D5" at 147.055,34.036 h3 r90
  text "D5#" at 157.051,34.036 h3 r90
  text "E5" at 167.047,34.036 h3 r90
  text "F5" at 177.043,34.036 h3 r90
  text "F5#" at 187.039,34.036 h3 r90
  text "G5" at 197.035,34.036 h3 r90
  text "G5#" at 207.031,34.036 h3 r90
  text "A5" at 217.027,34.036 h3 r90
  text "A5#" at 227.023,34.036 h3 r90
  text "B5" at 237.019,34.036 h3 r90
  text "C6" at 247.015,34.036 h3 r90
  text "C6#" at 257.011,34.036 h3 r90
  text "D6" at 267.007,34.036 h3 r90
  text "D6#" at 277.003,34.036 h3 r90
  text "E6" at 286.999,34.036 h3 r90
  text "F6" at 296.995,34.036 h3 r90
  text "F6#" at 306.991,34.036 h3 r90
  text "G6" at 316.987,34.036 h3 r90
  text "G6#" at 326.983,34.036 h3 r90
  text "A6" at 336.979,34.036 h3 r90
  text "A6#" at 346.975,34.036 h3 r90
  text "B6" at 356.97,34.036 h3 r90
  text "C7" at 366.966,34.036 h3 r90
  text "C7#" at 376.962,34.036 h3 r90
  text "D7" at 386.958,34.036 h3 r90
  text "D7#" at 396.954,34.036 h3 r90
  text "E7" at 406.95,34.036 h3 r90
  text "F7" at 416.946,34.036 h3 r90
  text "F7#" at 426.942,34.036 h3 r90
  text "G7" at 436.938,34.036 h3 r90
  text "G7#" at 446.934,34.036 h3 r90
  text "A7" at 456.93,34.036 h3 r90
  text "A7#" at 466.926,34.036 h3 r90
  text "B7" at 476.922,34.036 h3 r90
  text "C8" at 486.918,34.036 h3 r90
  text "RH0" at 272.378,0.889 h3 r90
  text "VO-" at 30.734,0.635 h3 r90
  text "LEA" at 44.159,0.635 h3 r90
  text "DEM" at 57.583,0.635 h3 r90
  text "VO+" at 71.008,0.635 h3 r90
  text "TE-" at 84.433,0.635 h3 r90
  text "TE+" at 97.857,0.635 h3 r90
  text "FIN" at 111.282,0.635 h3 r90
  text "SIN" at 124.707,0.635 h3 r90
  text "RHY" at 138.131,0.635 h3 r90
  text "DRU" at 151.556,0.635 h3 r90
  text "DR3" at 164.98,0.635 h3 r90
  text "DR4" at 178.405,0.635 h3 r90
  text "STO" at 191.83,0.635 h3 r90
  text "reP" at 205.254,0.635 h3 r90
  text "Fil" at 218.679,0.635 h3 r90
  text "1K1" at 232.104,0.635 h3 r90
  text "RH6" at 245.528,0.635 h3 r90
  text "RH5" at 258.953,0.635 h3 r90
  text "RH9" at 285.802,0.635 h3 r90
  text "RH1" at 299.227,0.635 h3 r90
  text "RH2" at 312.652,0.635 h3 r90
  text "RH7" at 326.076,0.635 h3 r90
  text "RH8" at 339.501,0.635 h3 r90
  text "DR7" at 352.925,0.635 h3 r90
  text "DR8" at 366.35,0.635 h3 r90
  text "DR6" at 379.775,0.635 h3 r90
  text "DR5" at 393.199,0.635 h3 r90
  text "RH4" at 406.624,0.635 h3 r90
  text "RH3" at 420.049,0.635 h3 r90
  text "DR2" at 433.473,0.635 h3 r90
  text "DR1" at 446.898,0.635 h3 r90
  text "TO1" at 460.323,0.635 h3 r90
  text "TO2" at 473.747,0.635 h3 r90
  text "REC" at 487.172,0.635 h3 r90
